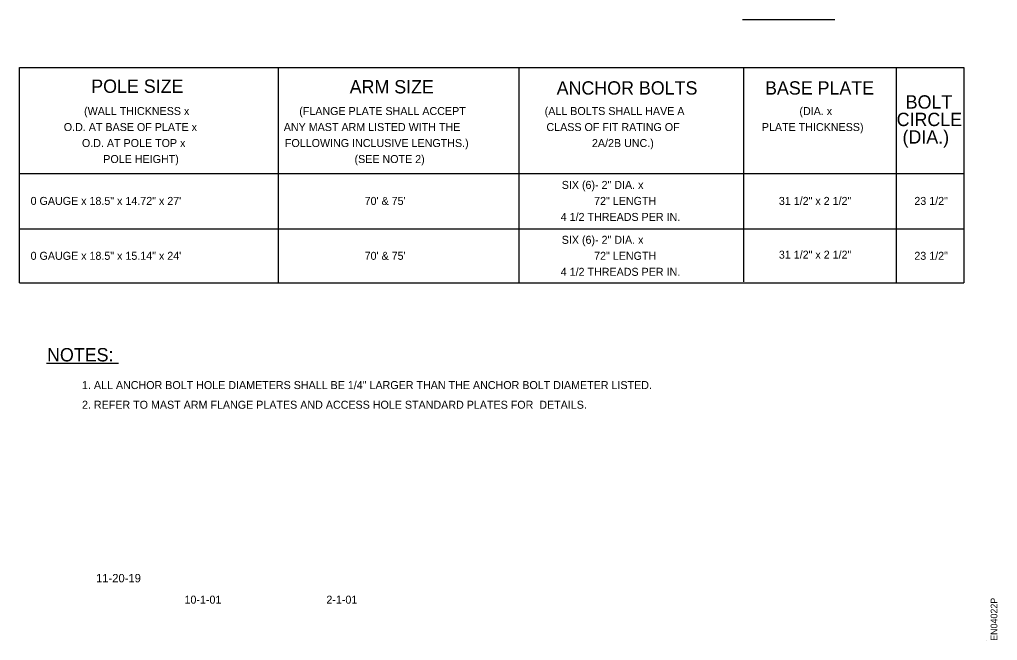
# Model space of a CAD drawing. Extents: x 101.85 to 109.18, y 93.43 to 103.17.
# Drawn here: x 101.85 to 109.18, y 93.43 to 98.08 of the extents above; entities that cross this region are included whole.
import ezdxf

# ---------------------------------------------------------------- set-up
doc = ezdxf.new("R2010")
doc.units = 0
for name, color, linetype in [('APPROVAL-OLD', 7, 'Continuous'), ('DETL-NOTE', 7, 'Continuous'), ('DETL-TITL', 7, 'Continuous'), ('EN', 7, 'Continuous'), ('TTLB-TEXT', 7, 'Continuous')]:
    doc.layers.add(name, color=color, linetype=linetype)

msp = doc.modelspace()

# ---------------------------------------------------------------- linework, layer by layer
at = {"layer": 'DETL-NOTE'}
for p, q in [((101.8456, 96.1097), (101.8456, 97.7261)), ((101.8456, 97.7261), (108.9249, 97.7261)), ((108.9249, 97.7261), (108.9249, 96.1094)), ((102.0486, 95.5079), (102.5862, 95.5079))]:
    msp.add_line(p, q, dxfattribs=at)
for points in [[(103.7832, 97.7261), (103.7832, 96.1104)], [(105.5882, 97.7261), (105.5882, 96.1094)], [(107.2729, 97.7261), (107.2729, 96.1166)], [(108.4179, 97.7261), (108.4179, 96.1108)], [(101.8456, 96.9307), (108.9249, 96.9307)], [(101.8456, 96.5149), (108.9249, 96.5149)], [(101.8456, 96.1097), (108.9249, 96.1097)]]:
    msp.add_lwpolyline(points, dxfattribs=at)
at = {"layer": 'DETL-TITL'}
msp.add_line((107.2665, 98.0845), (107.9568, 98.0845), dxfattribs=at)
at = {"layer": 'TTLB-TEXT'}
msp.add_line((109.0914, 93.4283), (109.0914, 93.4283), dxfattribs=at)

# ---------------------------------------------------------------- texts
at = {"layer": 'APPROVAL-OLD'}
for s, p in [('10-1-01', (103.0821, 93.7041)), ('2-1-01', (104.1458, 93.7041))]:
    msp.add_text(s, height=0.06, dxfattribs=at).set_placement(p)
at = {"layer": 'DETL-NOTE'}
for s, height, p in [('POLE SIZE', 0.1, (102.3831, 97.5348)), ('ARM SIZE', 0.1, (104.3206, 97.5305)), ('ANCHOR BOLTS', 0.1, (105.8724, 97.5217)), ('BASE PLATE', 0.1, (107.4346, 97.5217)), ('BOLT', 0.1, (108.489, 97.4166)), ('(WALL THICKNESS x', 0.06, (102.3292, 97.3684)), ('(FLANGE PLATE SHALL ACCEPT', 0.06, (103.9423, 97.3684)), ('(ALL BOLTS SHALL HAVE A', 0.06, (105.7824, 97.3684)), ('(DIA. x', 0.06, (107.6923, 97.3684)), ('CIRCLE', 0.1, (108.4213, 97.2855)), ('O.D. AT BASE OF PLATE x', 0.06, (102.1772, 97.2484)), ('ANY MAST ARM LISTED WITH THE', 0.06, (103.8264, 97.2484)), ('CLASS OF FIT RATING OF', 0.06, (105.7958, 97.2484)), ('PLATE THICKNESS)', 0.06, (107.4106, 97.2484)), ('(DIA.)', 0.1, (108.4653, 97.1544)), ('O.D. AT POLE TOP x', 0.06, (102.3133, 97.1284)), ('FOLLOWING INCLUSIVE LENGTHS.)', 0.06, (103.8349, 97.1284)), ('2A/2B UNC.)', 0.06, (106.1368, 97.1284)), ('POLE HEIGHT)', 0.06, (102.4733, 97.0084)), ('(SEE NOTE 2)', 0.06, (104.3569, 97.0084)), ('SIX (6)- 2" DIA. x', 0.06, (105.9104, 96.8144)), ('0 GAUGE x 18.5" x 14.72" x 27\'', 0.06, (101.9284, 96.6944)), ("70' & 75'", 0.06, (104.4326, 96.6944)), ('72" LENGTH', 0.06, (106.1531, 96.6944)), ('31 1/2" x 2 1/2"', 0.06, (107.5381, 96.6944)), ('23 1/2"', 0.06, (108.5538, 96.6944)), ('4 1/2 THREADS PER IN.', 0.06, (105.9027, 96.5744)), ('SIX (6)- 2" DIA. x', 0.06, (105.9104, 96.4027)), ('0 GAUGE x 18.5" x 15.14" x 24\'', 0.06, (101.9284, 96.2827)), ("70' & 75'", 0.06, (104.4326, 96.2827)), ('72" LENGTH', 0.06, (106.1531, 96.2827)), ('31 1/2" x 2 1/2"', 0.06, (107.5381, 96.2912)), ('23 1/2"', 0.06, (108.5538, 96.2827)), ('4 1/2 THREADS PER IN.', 0.06, (105.9027, 96.1627)), ('NOTES:', 0.1, (102.0518, 95.5209)), ('1. ALL ANCHOR BOLT HOLE DIAMETERS SHALL BE 1/4" LARGER THAN THE ANCHOR BOLT DIAMETER LISTED.', 0.06, (102.3137, 95.3134)), ('2. REFER TO MAST ARM FLANGE PLATES AND ACCESS HOLE STANDARD PLATES FOR  DETAILS.', 0.06, (102.3137, 95.1659))]:
    msp.add_text(s, height=height, dxfattribs=at).set_placement(p)
at = {"layer": 'EN'}
msp.add_text('EN04022P', height=0.05, rotation=90, dxfattribs=at).set_placement((109.1762, 93.4251))
at = {"layer": 'TTLB-TEXT'}
msp.add_text('11-20-19', height=0.06282, dxfattribs=at).set_placement((102.4189, 93.864))

doc.saveas('drawing.dxf')
